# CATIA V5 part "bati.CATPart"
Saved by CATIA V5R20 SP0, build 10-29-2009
Part number: bati
Bounding box of the stored display mesh (mm): x -51 to 41, y -321.578 to 407.422, z -260.841 to 159.204
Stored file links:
  D:\Dropbox\IAO_2012\IAO_2012_748_omeyer\omeyer\omeyer\bati.CATPart
  U:\Projet IAO\omeyer\Catia\Ass_748_skl.CATProduct
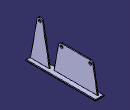
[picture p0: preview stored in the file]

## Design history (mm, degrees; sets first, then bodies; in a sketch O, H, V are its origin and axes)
Set1
  Plane1 "PlanRef": linked copy from another document
  Point1 "PointA": linked copy from another document
  Point2 "PointD": linked copy from another document
  DatumPoint1 "PointG": linked copy from another document
Body1 (main body)
  Sketch1 on Plane1, origin (0, 0, 0), H (0, 1, 0), V (0, 0, 1)
    arc A1 centre (0, 0) radius 30 from (0, 30) to (-29.5442, 5.2094) ccw
    point P1 (0, 0)
    arc A2 centre (300, 0) radius 30 from (329.5442, 5.2094) to (300, 30) ccw
    point P2 (300, 0)
    reference projected point E1 (0, 0) from Point1
    reference projected point E2 (300, 0) from Point2
    line L1 (300, 30) -> (0, 30)
    line L2 (329.5442, 5.2094) -> (374.6928, -250.8406)
    line L3 (-29.5442, 5.2094) -> (-74.6928, -250.8406)
    line L4 (-74.6928, -250.8406) -> (374.6928, -250.8406)
    circle A3 centre (300, 0) radius 15
    point P9 (300, 0)
    circle A4 centre (0, 0) radius 15
    point P10 (0, 0)
    reference projected point E3 (300, 0) from Point2
    reference projected point E4 (0, 0) from Point1
    radius A2 = 30
    radius A1 = 30
    angle L2 L4 = 80
    angle L3 L4 = 80
    length L2 = 260
    radius A4 = 15
    radius A3 = 15
    coincidence: P1 E1, P2 E2, P9 E3, P10 E4
    tangency: L1 A1, L1 A2, L2 A2, L3 A1
    horizontal: L4 H
  Pad1: profile Sketch1, direction (-1, 0, 0), length 10, opposite side length -20
  Sketch2 on Plane1, origin (0, 0, 0), H (0, 1, 0), V (0, 0, 1)
    arc A1 centre (-214, 129.244) radius 30 from (-184.4558, 134.4534) to (-243.5442, 134.4534) ccw
    point P1 (-214, 129.244)
    reference projected point E1 (-214, 129.244) from DatumPoint1
    line L1 (-243.5442, 134.4534) -> (-311.482, -250.8406)
    line L2 (-184.4558, 134.4534) -> (-116.518, -250.8406)
    line L3 (-116.518, -250.8406) -> (-311.482, -250.8406)
    reference projected line E2 (-74.6928, -250.8406) -> (374.6928, -250.8406) from edge [face of Pad1 from Sketch1.L4 | end face of Pad1]
    circle A2 centre (-214, 129.244) radius 15
    point P6 (-214, 129.244)
    reference projected point E3 (-214, 129.244) from DatumPoint1
    radius A1 = 30
    angle L2 L3 = 80
    angle L1 L3 = 80
    radius A2 = 15
    coincidence: P1 E1, L3 E2, P6 E3
    horizontal: L3 H
    tangency: L2 A1, A1 L1
  Pad2: profile Sketch2, direction (-1, 0, 0), length 10
  Sketch3 on face of Pad1 from Sketch1.L4, origin (0, 0, -250.8406), H (1, 0, 0), V (0, -1, 0)
    line L1 (-51, 321.5784) -> (41, 321.5784)
    line L2 (41, 321.5784) -> (41, -407.4216)
    line L3 (41, -407.4216) -> (-51, -407.4216)
    line L4 (-51, -407.4216) -> (-51, 321.5784)
    horizontal: L1 H, L3 H
    vertical: L2 V, L4 V
  Pad3: profile Sketch3, direction (0, 0, -1), length 10
  Chamfer1: length 5, angle 45, on edge [start face of Pad3 | face of Pad3 from Sketch3.L2]; edge [start face of Pad3 | face of Pad3 from Sketch3.L3]; edge [start face of Pad3 | face of Pad3 from Sketch3.L4]; edge [start face of Pad3 | face of Pad3 from Sketch3.L1]
  Fillet1: radius 5, on edge [face of Pad2 from Sketch2.L1 | start face of Pad3]; edge [start face of Pad3 | face of Pad1 from Sketch1.L3]; edge [start face of Pad3 | face of Pad2 from Sketch2.L2]; edge [face of Pad1 from Sketch1.L2 | start face of Pad3]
